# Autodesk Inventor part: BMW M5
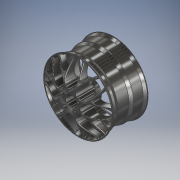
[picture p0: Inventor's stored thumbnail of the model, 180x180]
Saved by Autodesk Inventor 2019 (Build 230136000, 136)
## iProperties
Created: 2019-10
Part Number: BMW M5
Material: Acero inoxidable
Document SubType Name: Modeling
Designer: USUARIO
Density: 8 g/cm^3
Appearance: Cromo - Negro Pulido
Author: USUARIO
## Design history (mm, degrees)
sketch "Boceto1"
  geometry: L1 (0, 0)-(250, 0); L2 (0, 241.3)-(0, 237.3); L3 (0, 237.3)-(20.785, 225.3); L4 (20.785, 225.3)-(40.785, 225.3); L5 (40.785, 225.3)-(61.569, 213.3); L6 (61.569, 213.3)-(141.569, 213.3); L7 (141.569, 213.3)-(162.354, 225.3); L8 (162.354, 225.3)-(229.215, 225.3); L9 (229.215, 225.3)-(250, 237.3); L10 (250, 237.3)-(250, 241.3)
  constraints: 20 end point, 4 parallel, 2 horizontal, 2 perpendicular, 2 point on line, 1 collinear, 1 horizontal alignment, 1 vertical
  dimensions: "d0" = 250 distance of L1.start L1.end; "d1" = 4 distance of L2.start L2.end; "d2" = 60 deg angle of L2 L3; "d3" = 30 deg angle of L8 L7; "d4" = 12 vertical distance of L2.end L3.end; "d5" = 12 vertical distance of L4.end L5.end; "d6" = 80 distance of L5.end L6.end; "d7" = 20 distance of L3.end L4.end; "d8" = 482.6 diameter of L2.start L1
feature "SuperficieRevolución1" sketch "Boceto1" dims angle "d9" = 90 deg
fillet "Empalme1" dims "d10" = 4
feature "Engrosado1" dims "d11" = 3
node "Plano de trabajo2"
  node "Plano de trabajo1"
sketch "Boceto2" dims "d14" = 120
  geometry: L1 (0, 60)-(57.063, 18.541); L2 (57.063, 18.541)-(35.267, -48.541); L3 (35.267, -48.541)-(-35.267, -48.541); L4 (-35.267, -48.541)-(-57.063, 18.541); L5 (-57.063, 18.541)-(0, 60); C1 r 36.25 at (0, 0); C2 r 6 at (0, 60); C3 r 70 at (0, 0); 3 further points
  constraints: 10 end point, 5 coincident, 3 centre point, 1 horizontal, 1 vertical alignment, 13 other
  dimensions: "d13" = 72.5 diameter of C1; "d15" = 12 diameter of C2; "d16" = 140 diameter of C3
extrude "Extrusión1" new body sketch "Boceto2" distance "d17" = 592.5; taper "d18" = 0 deg
extrude "Extrusión2" join sketch "Boceto2" distance "d19" = 592.5; taper "d20" = 0 deg
sketch "Boceto3"
  geometry: L1 (96, 60)-(-201.46, 60); L2 (-201.46, 60)-(-201.46, 72); L3 (-201.46, 72)-(10, 72); L4 (10, 72)-(16, 66); L5 (16, 66)-(96, 66); L6 (96, 66)-(96, 60); 1 further point
  constraints: 12 end point, 3 perpendicular, 1 horizontal, 1 parallel
  dimensions: "d21" = 12 diameter of L5 L1; "d22" = 24 diameter of L3 L1; "d23" = 45 deg angle of L5 L4; "d24" = 80 distance of L4.end L5.end
revolve "Revolución1" sketch "Boceto3" stored, may be unused: angle "d25" = 90 deg
pattern_circular "Patrón circular1" dims angle "d27" = 360 deg
sketch "Boceto4"
  geometry: L1 (2, -236.145)-(19.856, -225.836) reference; L2 (21.856, -225.3)-(39.713, -225.3) reference; L3 (41.713, -224.764)-(60.641, -213.836) reference; L4 (62.641, -213.3)-(140.497, -213.3) reference; L5 (142.497, -213.836)-(161.426, -224.764) reference; L6 (163.426, -225.3)-(228.144, -225.3) reference; L7 (230.144, -225.836)-(248, -236.145) reference; L8 (250, -239.609)-(250, -241.3) reference; L9 (250, -241.3)-(247, -241.3) reference; L10 (247, -241.3)-(247, -239.609) reference; L11 (246.5, -238.743)-(228.644, -228.434) reference; L12 (228.144, -228.3)-(163.426, -228.3) reference; L13 (159.926, -227.362)-(140.997, -216.434) reference; L14 (140.497, -216.3)-(62.641, -216.3) reference; L15 (62.141, -216.434)-(43.213, -227.362) reference; L16 (39.713, -228.3)-(21.856, -228.3) reference; L17 (21.356, -228.434)-(3.5, -238.743) reference; L18 (3, -239.609)-(3, -241.3) reference; L19 (3, -241.3)-(0, -241.3) reference; L20 (0, -241.3)-(0, -239.609) reference; L21 (0, 239.609)-(0, 241.3) reference; L22 (0, 241.3)-(3, 241.3) reference; L23 (3, 241.3)-(3, 239.609) reference; L24 (3.5, 238.743)-(21.356, 228.434) reference; L25 (21.856, 228.3)-(39.713, 228.3) reference; L26 (43.213, 227.362)-(62.141, 216.434) reference; L27 (62.641, 216.3)-(140.497, 216.3) reference; L28 (140.997, 216.434)-(159.926, 227.362) reference; L29 (163.426, 228.3)-(228.144, 228.3) reference; L30 (228.644, 228.434)-(246.5, 238.743) reference; L31 (247, 239.609)-(247, 241.3) reference; L32 (247, 241.3)-(250, 241.3) reference; L33 (250, 241.3)-(250, 239.609) reference; L34 (248, 236.145)-(230.144, 225.836) reference; L35 (228.144, 225.3)-(163.426, 225.3) reference; L36 (161.426, 224.764)-(142.497, 213.836) reference; L37 (140.497, 213.3)-(62.641, 213.3) reference; L38 (60.641, 213.836)-(41.713, 224.764) reference; L39 (39.713, 225.3)-(21.856, 225.3) reference; L40 (19.856, 225.836)-(2, 236.145) reference; L41 (688.5, -70)-(96, -70) reference; L42 (96, -70)-(96, -36.25) reference; L43 (96, -36.25)-(-496.5, -36.25) reference; L44 (-496.5, -36.25)-(-496.5, 36.25) reference; L45 (-496.5, 36.25)-(96, 36.25) reference; L46 (96, 36.25)-(96, 54) reference; L47 (96, 54)-(16, 54) reference; L48 (16, 54)-(10, 48) reference; L49 (10, 48)-(-201.46, 48) reference; L50 (-201.46, 48)-(-201.46, 72) reference; L51 (-201.46, 72)-(10, 72) reference; L52 (10, 72)-(16, 66) reference; L53 (16, 66)-(96, 66) reference; L54 (96, 66)-(96, 70) reference; L55 (96, 70)-(688.5, 70) reference; L56 (688.5, 70)-(688.5, -70) reference; L57 (0, 239.609)-(0, 182.738); L58 (0, 182.738)-(-123.597, 93.076); L59 (-123.597, 93.076)-(-35.104, 48); L60 (-35.104, 48)-(-35.104, 0); L61 (-35.104, 0)-(96, 0); L62 (96, -36.25)-(96, 36.25) reference; L63 (60.641, 213.836)-(41.713, 224.764) reference; L64 (96, -70)-(96, 70) reference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; A1 r 4 centre (4, -239.609) between (2, -236.145) and (0, -239.609) reference; A2 r 4 centre (21.856, -229.3) between (21.856, -225.3) and (19.856, -225.836) reference; A3 r 4 centre (39.713, -221.3) between (39.713, -225.3) and (41.713, -224.764) reference; A4 r 4 centre (62.641, -217.3) between (62.641, -213.3) and (60.641, -213.836) reference; A5 r 4 centre (140.497, -217.3) between (142.497, -213.836) and (140.497, -213.3) reference; A6 r 4 centre (163.426, -221.3) between (161.426, -224.764) and (163.426, -225.3) reference; A7 r 4 centre (228.144, -229.3) between (230.144, -225.836) and (228.144, -225.3) reference; A8 r 4 centre (246, -239.609) between (250, -239.609) and (248, -236.145) reference; A9 r 1 centre (246, -239.609) between (247, -239.609) and (246.5, -238.743) reference; A10 r 1 centre (228.144, -229.3) between (228.644, -228.434) and (228.144, -228.3) reference; A11 r 7 centre (163.426, -221.3) between (159.926, -227.362) and (163.426, -228.3) reference; A12 r 1 centre (140.497, -217.3) between (140.997, -216.434) and (140.497, -216.3) reference; A13 r 1 centre (62.641, -217.3) between (62.641, -216.3) and (62.141, -216.434) reference; A14 r 7 centre (39.713, -221.3) between (39.713, -228.3) and (43.213, -227.362) reference; A15 r 1 centre (21.856, -229.3) between (21.856, -228.3) and (21.356, -228.434) reference; A16 r 1 centre (4, -239.609) between (3.5, -238.743) and (3, -239.609) reference; A17 r 4 centre (4, 239.609) between (0, 239.609) and (2, 236.145) reference; A18 r 1 centre (4, 239.609) between (3, 239.609) and (3.5, 238.743) reference; A19 r 1 centre (21.856, 229.3) between (21.356, 228.434) and (21.856, 228.3) reference; A20 r 7 centre (39.713, 221.3) between (43.213, 227.362) and (39.713, 228.3) reference; A21 r 1 centre (62.641, 217.3) between (62.141, 216.434) and (62.641, 216.3) reference; A22 r 1 centre (140.497, 217.3) between (140.497, 216.3) and (140.997, 216.434) reference; A23 r 7 centre (163.426, 221.3) between (163.426, 228.3) and (159.926, 227.362) reference; A24 r 1 centre (228.144, 229.3) between (228.144, 228.3) and (228.644, 228.434) reference; A25 r 1 centre (246, 239.609) between (246.5, 238.743) and (247, 239.609) reference; A26 r 4 centre (246, 239.609) between (248, 236.145) and (250, 239.609) reference; A27 r 4 centre (228.144, 229.3) between (228.144, 225.3) and (230.144, 225.836) reference; A28 r 4 centre (163.426, 221.3) between (163.426, 225.3) and (161.426, 224.764) reference; A29 r 4 centre (140.497, 217.3) between (140.497, 213.3) and (142.497, 213.836) reference; A30 r 4 centre (62.641, 217.3) between (60.641, 213.836) and (62.641, 213.3) reference; A31 r 4 centre (39.713, 221.3) between (41.713, 224.764) and (39.713, 225.3) reference; A32 r 4 centre (21.856, 229.3) between (19.856, 225.836) and (21.856, 225.3) reference; 1 further point
  constraints: 3 point on line, 2 end point, 1 midpoint, 6 other
revolve "Revolución2" sketch "Boceto4" stored, may be unused: angle "d29" = 90 deg
feature "Combinar1"
  node "Centro"
node "Plano de trabajo3"
sketch "Boceto5" dims "d31" = 150
  geometry: L1 (0, 0)-(308.395, 0); L2 (0, 0)-(284.92, 118.018); L3 (0, 0)-(218.068, 218.068); L4 (0, 0)-(118.018, 284.92); L5 (0, 0)-(0, 308.395); L6 (0, 0)-(-118.018, 284.92); L7 (0, 0)-(-218.068, 218.068); L8 (0, 0)-(-284.92, 118.018); L9 (0, 0)-(-308.395, 0); L10 (0, 0)-(-284.92, -118.018); L11 (0, 0)-(-218.068, -218.068); L12 (0, 0)-(-118.018, -284.92); L13 (0, 0)-(0, -308.395); L14 (0, 0)-(118.018, -284.92); L15 (0, 0)-(218.068, -218.068); L16 (0, 0)-(284.92, -118.018); L17 (266.086, -15.533)-(118.018, -64.017); L18 (118.018, -64.017)-(75, -31.066); L19 (75, -31.066)-(75, 0); L20 (266.086, 15.533)-(118.018, 64.017); L21 (118.018, 64.017)-(75, 31.066); L22 (75, 31.066)-(75, 0); L23 (266.086, -15.533)-(266.086, 15.533); L24 (199.135, 177.168)-(177.168, 199.135); L25 (199.135, 177.168)-(128.718, 38.185); L26 (128.718, 38.185)-(75, 31.066); L27 (75, 31.066)-(53.033, 53.033); L28 (177.168, 199.135)-(38.185, 128.718); L29 (38.185, 128.718)-(31.066, 75); L30 (31.066, 75)-(53.033, 53.033); L31 (15.533, 266.086)-(-15.533, 266.086); L32 (15.533, 266.086)-(64.017, 118.018); L33 (64.017, 118.018)-(31.066, 75); L34 (31.066, 75)-(0, 75); L35 (-15.533, 266.086)-(-64.017, 118.018); L36 (-64.017, 118.018)-(-31.066, 75); L37 (-31.066, 75)-(0, 75); L38 (-177.168, 199.135)-(-199.135, 177.168); L39 (-177.168, 199.135)-(-38.185, 128.718); L40 (-38.185, 128.718)-(-31.066, 75); L41 (-31.066, 75)-(-53.033, 53.033); L42 (-199.135, 177.168)-(-128.718, 38.185); L43 (-128.718, 38.185)-(-75, 31.066); L44 (-75, 31.066)-(-53.033, 53.033); L45 (-266.086, 15.533)-(-266.086, -15.533); L46 (-266.086, 15.533)-(-118.018, 64.017); L47 (-118.018, 64.017)-(-75, 31.066); L48 (-75, 31.066)-(-75, 0); L49 (-266.086, -15.533)-(-118.018, -64.017); L50 (-118.018, -64.017)-(-75, -31.066); L51 (-75, -31.066)-(-75, 0); L52 (-199.135, -177.168)-(-177.168, -199.135); L53 (-199.135, -177.168)-(-128.718, -38.185); L54 (-128.718, -38.185)-(-75, -31.066); L55 (-75, -31.066)-(-53.033, -53.033); L56 (-177.168, -199.135)-(-38.185, -128.718); L57 (-38.185, -128.718)-(-31.066, -75); L58 (-31.066, -75)-(-53.033, -53.033); L59 (-15.533, -266.086)-(15.533, -266.086); L60 (-15.533, -266.086)-(-64.017, -118.018); L61 (-64.017, -118.018)-(-31.066, -75); L62 (-31.066, -75)-(0, -75); L63 (15.533, -266.086)-(64.017, -118.018); L64 (64.017, -118.018)-(31.066, -75)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; 2 further points
  constraints: 50 end point, 5 symmetric about line, 4 point on line, 1 coincident, 1 horizontal, 1 horizontal alignment, 1 vertical, 1 vertical alignment, 236 other
  dimensions: "d34" = 360 deg dimension on point (0, 0) L1.end (derived); "d38" = 360 deg dimension on point (0, 0) L17.start (derived)
extrude "Extrusión3" cut sketch "Boceto5" distance "d40" = 592.5; taper "d41" = -1 deg
fillet "Empalme2" dims "d42" = 5
fillet "Empalme3" dims "d43" = 8
pattern_circular "Patrón circular2" dims angle "d45" = 360 deg
fillet "Empalme4" dims "d47" = 1
fillet "Empalme5" dims "d48" = 5
feature "Combinar2"
  node "Aro"
fillet "Empalme6" dims "d49" = 4
fillet "Empalme7" dims "d50" = 4
fillet "Empalme8" dims "d51" = 4
fillet "Empalme9" dims "d52" = 4
fillet "Empalme10" dims "d53" = 4
fillet "Empalme11" dims "d54" = 4
fillet "Empalme12" dims "d55" = 4
fillet "Empalme13" dims "d56" = 4
node "Sup1"
node "Sólido3"
node "Proyectar aristas de corte1"
other parameters: "et" = 29, "d30" = -69.25
